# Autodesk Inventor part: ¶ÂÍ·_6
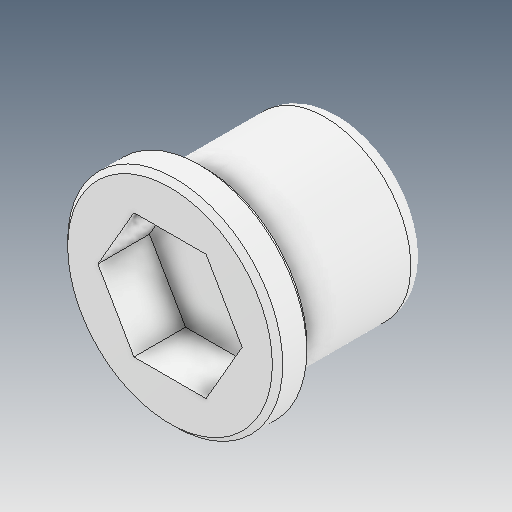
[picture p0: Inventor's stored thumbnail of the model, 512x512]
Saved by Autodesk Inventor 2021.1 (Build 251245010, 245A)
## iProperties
Created: 2021-06
Part Number: ¶ÂÍ·_6
Material: Ogólny
Document SubType Name: Modeling
Designer: user
Density: 1 g/cm^3
Appearance: Domyślna
Author: user
Revision Number: ÈÎºÎ
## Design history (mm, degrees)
feature "ÊäÈë1"
node "Bryła1"
